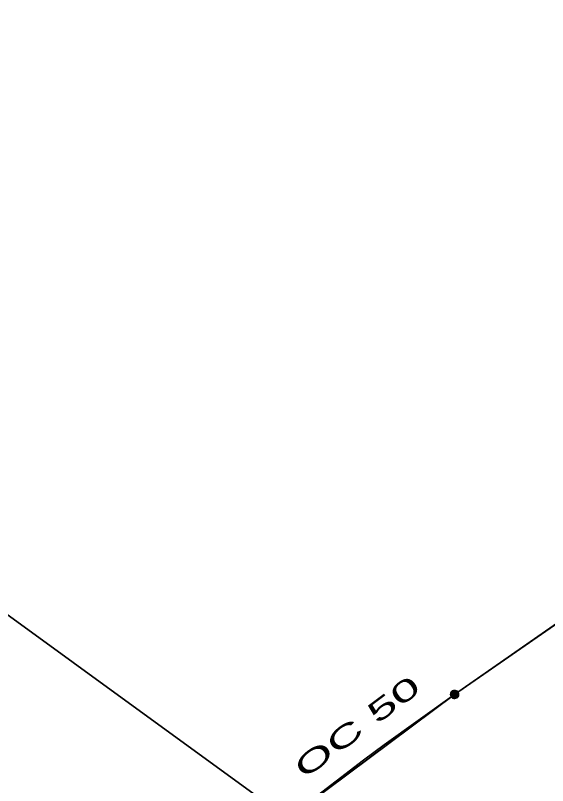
# Model space of a CAD drawing. Extents: x -873619 to -867639, y -1015082 to -1012326.
# Drawn here: x -868136.92 to -868108.69, y -1012849.97 to -1012809.1 of the extents above; entities that cross this region are included whole.
import ezdxf

# ---------------------------------------------------------------- set-up
doc = ezdxf.new("R2010")
doc.units = 0
doc.header["$LTSCALE"] = 0.44
for name, color, linetype, lineweight in [('1', 7, 'Continuous', 13), ('12', 7, 'Continuous', 13), ('21', 7, 'Continuous', 35)]:
    doc.layers.add(name, color=color, linetype=linetype, lineweight=lineweight)

msp = doc.modelspace()

# ---------------------------------------------------------------- linework, layer by layer
at = {"layer": '1', "lineweight": 35}
msp.add_line((-868107.61, -1012840.95), (-868113.62, -1012845.13), dxfattribs=at)
for points in [[(-868093, -1012833.748), (-868101.39, -1012837.01), (-868107.58, -1012840.931), (-868113.62, -1012845.13), (-868123.8, -1012852.73), (-868130.75, -1012859.04), (-868135.78, -1012863.43), (-868135.449, -1012863.638)], [(-868113.62, -1012845.13), (-868117.359, -1012847.8), (-868118.459, -1012848.62), (-868123.8, -1012852.73), (-868130.75, -1012859.04)]]:
    msp.add_lwpolyline(points, dxfattribs=at)
at = {"layer": '12'}
for points in [[(-868113.389, -1012845.13), (-868113.395, -1012845.078), (-868113.412, -1012845.028), (-868113.441, -1012844.984), (-868113.478, -1012844.947), (-868113.523, -1012844.92), (-868113.573, -1012844.903), (-868113.626, -1012844.899), (-868113.678, -1012844.906), (-868113.727, -1012844.925), (-868113.77, -1012844.954), (-868113.806, -1012844.993), (-868113.832, -1012845.038), (-868113.848, -1012845.089), (-868113.851, -1012845.141), (-868113.843, -1012845.193), (-868113.823, -1012845.242), (-868113.792, -1012845.285), (-868113.753, -1012845.319), (-868113.707, -1012845.345), (-868113.656, -1012845.359), (-868113.603, -1012845.361), (-868113.552, -1012845.351), (-868113.504, -1012845.33), (-868113.461, -1012845.299), (-868113.427, -1012845.258), (-868113.403, -1012845.212), (-868113.391, -1012845.161)], [(-868113.419, -1012845.13), (-868113.425, -1012845.081), (-868113.442, -1012845.035), (-868113.47, -1012844.995), (-868113.507, -1012844.963), (-868113.551, -1012844.941), (-868113.599, -1012844.93), (-868113.648, -1012844.93), (-868113.695, -1012844.943), (-868113.738, -1012844.967), (-868113.774, -1012845), (-868113.801, -1012845.041), (-868113.817, -1012845.088), (-868113.821, -1012845.137), (-868113.814, -1012845.185), (-868113.795, -1012845.23), (-868113.765, -1012845.27), (-868113.727, -1012845.301), (-868113.683, -1012845.321), (-868113.635, -1012845.331), (-868113.586, -1012845.329), (-868113.539, -1012845.314), (-868113.496, -1012845.289), (-868113.462, -1012845.255), (-868113.436, -1012845.213), (-868113.422, -1012845.166)], [(-868113.449, -1012845.13), (-868113.455, -1012845.085), (-868113.472, -1012845.043), (-868113.5, -1012845.008), (-868113.536, -1012844.981), (-868113.578, -1012844.964), (-868113.623, -1012844.959), (-868113.668, -1012844.965), (-868113.709, -1012844.984), (-868113.744, -1012845.012), (-868113.771, -1012845.049), (-868113.787, -1012845.091), (-868113.791, -1012845.136), (-868113.784, -1012845.181), (-868113.765, -1012845.222), (-868113.736, -1012845.256), (-868113.699, -1012845.282), (-868113.656, -1012845.298), (-868113.611, -1012845.301), (-868113.566, -1012845.293), (-868113.526, -1012845.273), (-868113.492, -1012845.244), (-868113.466, -1012845.206), (-868113.452, -1012845.163)], [(-868113.479, -1012845.13), (-868113.483, -1012845.089), (-868113.502, -1012845.052), (-868113.529, -1012845.021), (-868113.564, -1012845), (-868113.604, -1012844.989), (-868113.645, -1012844.991), (-868113.684, -1012845.004), (-868113.718, -1012845.028), (-868113.743, -1012845.06), (-868113.758, -1012845.098), (-868113.761, -1012845.139), (-868113.753, -1012845.179), (-868113.733, -1012845.215), (-868113.704, -1012845.244), (-868113.667, -1012845.263), (-868113.627, -1012845.271), (-868113.586, -1012845.267), (-868113.548, -1012845.252), (-868113.516, -1012845.226), (-868113.493, -1012845.192), (-868113.48, -1012845.153)], [(-868113.509, -1012845.13), (-868113.514, -1012845.094), (-868113.532, -1012845.062), (-868113.558, -1012845.037), (-868113.592, -1012845.022), (-868113.628, -1012845.019), (-868113.663, -1012845.027), (-868113.694, -1012845.047), (-868113.717, -1012845.075), (-868113.73, -1012845.109), (-868113.73, -1012845.146), (-868113.719, -1012845.181), (-868113.698, -1012845.21), (-868113.668, -1012845.231), (-868113.633, -1012845.241), (-868113.596, -1012845.239), (-868113.562, -1012845.225), (-868113.535, -1012845.202), (-868113.516, -1012845.17), (-868113.509, -1012845.135)], [(-868113.539, -1012845.13), (-868113.544, -1012845.099), (-868113.561, -1012845.073), (-868113.587, -1012845.056), (-868113.617, -1012845.049), (-868113.648, -1012845.053), (-868113.675, -1012845.07), (-868113.693, -1012845.094), (-868113.701, -1012845.125), (-868113.697, -1012845.155), (-868113.682, -1012845.183), (-868113.657, -1012845.202), (-868113.628, -1012845.211), (-868113.597, -1012845.208), (-868113.569, -1012845.194), (-868113.549, -1012845.17), (-868113.539, -1012845.141)], [(-868113.569, -1012845.13), (-868113.574, -1012845.106), (-868113.591, -1012845.088), (-868113.614, -1012845.079), (-868113.638, -1012845.082), (-868113.659, -1012845.096), (-868113.67, -1012845.118), (-868113.67, -1012845.143), (-868113.657, -1012845.164), (-868113.638, -1012845.178), (-868113.613, -1012845.181), (-868113.59, -1012845.172), (-868113.574, -1012845.154)], [(-868113.599, -1012845.13), (-868113.604, -1012845.115), (-868113.619, -1012845.109), (-868113.634, -1012845.113), (-868113.641, -1012845.127), (-868113.637, -1012845.142), (-868113.624, -1012845.151), (-868113.608, -1012845.148), (-868113.599, -1012845.136)]]:
    msp.add_lwpolyline(points, close=True, dxfattribs=at)
at = {"layer": '21'}
msp.add_lwpolyline([(-868376.717, -1012555.154), (-868316.566, -1012631.217), (-868240.045, -1012726.354), (-868207.711, -1012767.909), (-868167.337, -1012819.086), (-868122.692, -1012851.556), (-868075.313, -1012871.422), (-868043.707, -1012866.643), (-868020.287, -1012856.898)], dxfattribs=at)

# ---------------------------------------------------------------- texts
at = {"layer": '1', "width": 1.85}
msp.add_text('OC 50 ', height=1.1, rotation=37, dxfattribs=at).set_placement((-868121.601, -1012849.652))

doc.saveas('drawing.dxf')
